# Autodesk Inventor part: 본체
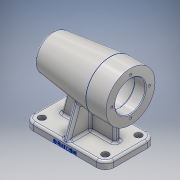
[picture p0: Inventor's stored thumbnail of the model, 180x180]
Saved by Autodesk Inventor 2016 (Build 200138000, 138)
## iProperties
Created: 2018-09
Part Number: 본체
Material: 알루미늄 6061
Document SubType Name: Modeling
Designer: 3sil_cad018
Density: 2.7 g/cm^3
Appearance: 알루미늄 - 평지
Mass: 731.35 g
Surface Area: 662.671 cm^2
Volume: 270.87 cm^3
Author: 3sil_cad018
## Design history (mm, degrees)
sketch "스케치1"
  geometry: L1 (0, 0)-(112, 0); L2 (112, 0)-(112, 34); L3 (112, 34)-(84, 34); L4 (3.73, 24.144)-(84, 34); L5 (6, 0)-(6, 10.5); L6 (6, 10.5)-(9, 10.5); L7 (9, 10.5)-(9, 16); L8 (9, 16)-(13, 16); L9 (13, 16)-(13, 17.5); L10 (13, 17.5)-(31, 17.5); L11 (31, 17.5)-(31, 21); L12 (31, 21)-(43, 21); L13 (43, 21)-(43, 24); L14 (43, 24)-(97, 24); L15 (97, 24)-(97, 21); L16 (97, 21)-(112, 21); L17 (112, 0)-(6, 0); A1 r 80 centre (80, 0) between (3.73, 24.144) and (0, 0)
  constraints: 34 end point, 11 perpendicular, 3 point on line, 3 vertical, 2 point on circle, 1 centre point, 1 horizontal, 1 parallel
  dimensions: "d0" = 112 distance from line of L2 L1.start; "d1" = 28 distance of L2.end L3.end; "d2" = 68 diameter of L3 L1; "d3" = 7 deg angle of L3 L4; "d4" = 80 radius of A1; "d6" = 42 diameter of L16 L1; "d7" = 15 distance of L15.end L16.end; "d8" = 48 diameter of L14 L1; "d9" = 42 diameter of L12 L1; "d10" = 35 diameter of L10 L1; "d11" = 32 diameter of L8 L17; "d12" = 21 diameter of L6 L17; "d13" = 54 distance of L13.end L14.end; "d14" = 18 distance of L9.end L10.end; "d15" = 3 distance of L5.end L6.end; "d16" = 4 distance of L7.end L8.end; "d17" = 12 distance of L11.end L12.end
revolve "회전1" stored, may be unused: angle "d5" = 90 deg
revolve "회전2" stored, may be unused: angle "d18" = 90 deg
sketch "스케치2"
  geometry: A1 r 26 centre (0, 0) between (-26, 0) and (26, 0); 3 further points
  constraints: 4 point on circle, 1 centre point, 1 coincident
  dimensions: "d19" = 52 diameter of A1
hole "구멍1" sketch "스케치2" at (-26, 0), (26, 0), (0, 26), (0, -26) diameter "d24" = 3.242; stored, may be unused: countersink angle "d28" = 90 deg, drill point angle "d30" = 118 deg; dims "d25" = 8, "d26" = 4, "d27" = 2, "d29" = 11
fillet "모깎기1" dims "d31" = 3
fillet "모깎기2" dims "d32" = 3
chamfer "모따기1" distance "d33" = 1; stored, may be unused: second distance "d34" = 2, angle "d35" = 45 deg
node "작업 평면1"
sketch "스케치3"
  geometry: L1 (0, 35)-(112, 35); L2 (112, 35)-(112, -35); L3 (112, -35)-(0, -35); L4 (0, -35)-(0, 35); L5 (112, -34)-(112, 34) reference; 2 further points
  constraints: 8 end point, 2 parallel, 1 collinear, 1 horizontal, 1 horizontal alignment, 1 midpoint, 1 perpendicular
  dimensions: "d37" = 112 distance of L1.start L1.end; "d38" = 70 distance of L3.end L1.start
extrude "돌출1" join sketch "스케치3" distance "d39" = 10; taper "d40" = 0 deg
fillet "모깎기3" dims "d41" = 0.3
fillet "모깎기4" dims "d42" = 12
fillet "모깎기5" dims "d43" = 3
sketch "스케치4"
  geometry: L1 (12, 35)-(100, 35) reference; L2 (112, 23)-(112, -23) reference; L3 (100, -35)-(12, -35) reference; L4 (0, -23)-(0, 23) reference; A1 r 12 centre (12, 23) between (12, 35) and (0, 23) reference; A2 r 12 centre (100, 23) between (112, 23) and (100, 35) reference; A3 r 12 centre (100, -23) between (100, -35) and (112, -23) reference; A4 r 12 centre (12, -23) between (0, -23) and (12, -35) reference; 1 further point
hole "구멍2" sketch "스케치4" at (12, 23), (100, 23), (100, -23), (12, -23) diameter "d44" = 5.5; stored, may be unused: countersink angle "d48" = 90 deg, drill point angle "d50" = 118 deg; dims "d45" = 8, "d46" = 9.5, "d47" = 5.4, "d49" = 11
sketch "스케치5"
  geometry: L1 (-100, -64)-(-12, -64) reference; L2 (-5.669, -24.382)-(-84, -34) reference; L3 (-18, -68.54)-(-29.432, -25.874); L4 (-29.432, -25.874)-(-94, -29.757); L5 (-94, -29.757)-(-94, -68.54); L6 (-84, 34)-(-84, -34) reference; L7 (-94, -68.54)-(-18, -68.54); L8 (-112, -67)-(-112, -74) reference; L9 (0, -74)-(0, -67) reference; L10 (-100, -67)-(-12, -67) reference; L11 (-100, -74)-(-100, -67) reference; L12 (-12, -74)-(-100, -74) reference; L13 (-12, -67)-(-12, -74) reference; 1 further point
  constraints: 8 end point, 1 parallel, 1 perpendicular
  dimensions: "d51" = 18 distance between parallel lines of L8 L5; "d52" = 105 deg angle of L3 L1; "d53" = 18 distance from line of L3.start L9
extrude "돌출2" join sketch "스케치5" stored distance "d54" = 8; taper "d55" = 0 deg
node "작업 평면2"
sketch "스케치6"
  geometry: L1 (10, 0)-(10, 46) reference; L2 (47.031, 23)-(7, 23); L3 (7, 23)-(7, -12); L4 (7, -12)-(52.198, 4.451); L5 (52.198, 4.451)-(47.031, 23); L6 (0, -12)-(7, -12) reference; L7 (10, 46)-(10, 0); L8 (7, 23)-(7, 58); L9 (7, 58)-(52.198, 41.549); L10 (52.198, 41.549)-(47.031, 23); L11 (40.236, 27)-(47.031, 27) reference; L12 (47.031, 19)-(40.236, 19) reference; C1 r 24.382 at (74, 23) reference; A1 r 34 centre (74, 23) between (40.236, 19) and (40.236, 27) reference; A2 r 3 centre (7, -9) between (7, -12) and (10, -9) reference; A3 r 3 centre (7, 55) between (10, 55) and (7, 58); 3 further points; 1 other entity
  constraints: 16 end point, 6 symmetric about line, 2 point on circle, 1 centre point, 1 horizontal alignment, 1 midpoint, 1 perpendicular, 2 other
extrude "돌출3" join sketch "스케치6" stored distance "d57" = 8; taper "d58" = 0 deg
sketch "스케치8"
  geometry: L1 (100, 0)-(100, 7) reference; L2 (100, 0)-(88, 0) reference; 2 further points
  constraints: 1 other
  dimensions: "d62" = 56 distance from line of L1 point (44, 3); "d63" = 3 distance from line of L2 point (44, 3)
feature "엠보싱1" sketch "스케치8" dims "d0" = 112, "d1" = 28, "d2" = 68, "d3" = 7 deg, "d4" = 80, "d6" = 42, "d7" = 15, "d8" = 48, "d9" = 42, "d10" = 35, "d11" = 32, "d12" = 21, "d13" = 54, "d14" = 18, "d15" = 3, "d16" = 4, "d17" = 12, "d64" = 0.5, "d65" = 0
fillet "모깎기9" dims "d66" = 3
fillet "모깎기10" dims "d67" = 3
fillet "모깎기11" dims "d68" = 3
node "솔리드1"
node "투영된 루프1"
node "투영된 루프2"
node "투영된 루프3"
other parameters: "d20" = 0.5, "d21" = 2, "d22" = 0, "d36" = -74
